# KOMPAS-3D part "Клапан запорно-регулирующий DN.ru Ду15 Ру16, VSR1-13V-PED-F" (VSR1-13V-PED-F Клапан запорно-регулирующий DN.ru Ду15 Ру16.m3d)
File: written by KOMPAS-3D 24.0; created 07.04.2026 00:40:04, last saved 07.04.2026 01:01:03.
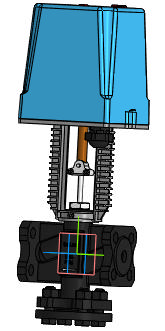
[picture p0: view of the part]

Document properties: Автор: R2D2; Полное имя файла: VSR1-13V-PED-F Клапан запорно-регулирующий DN.ru Ду15 Ру16.cdw

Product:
- Part/product: Клапан запорно-регулирующий DN.ru Ду15 Ру16  | designation VSR1-13V-PED-F
    Масса: 6.1
    Раздел спецификации: Прочие изделия
    Форматы листов документа: A3
    Примечание: D090-02884

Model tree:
1. Операция без истории:1  (labels: SHAPEOBJECT3D_ATTR_BUTT)

Expressions: VSR1-13V-PED-F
